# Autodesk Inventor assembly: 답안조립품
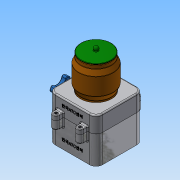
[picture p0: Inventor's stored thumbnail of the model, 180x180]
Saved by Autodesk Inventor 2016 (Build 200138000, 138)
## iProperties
Created: 2018-01
Part Number: 답안조립품
Material: 일반
Document SubType Name: Assembly
Designer: Administrator
Author: Administrator
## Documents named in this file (9)
- C:\Users\Administrator\Desktop\480107V1046\답안조립품.iam
- C:\Users\Administrator\Desktop\480107V1046\본체.ipt
- C:\Users\Administrator\Desktop\480107V1046\용기캡.ipt
- C:\Users\Administrator\Desktop\480107V1046\용기.ipt
- C:\Users\Administrator\Desktop\480107V1046\본체커버.ipt
- C:\Users\Administrator\Desktop\480107V1046\핸들축.ipt
- C:\Users\Administrator\Desktop\480107V1046\핸들.ipt
- C:\Users\Administrator\Desktop\480107V1046\볼트 M3x12.ipt
- C:\Users\Administrator\Desktop\480107V1046\볼트 M4x12.ipt
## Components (2 placed, 2 different names)
1. 핸들축:1
2. 핸들:1
